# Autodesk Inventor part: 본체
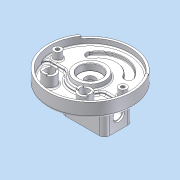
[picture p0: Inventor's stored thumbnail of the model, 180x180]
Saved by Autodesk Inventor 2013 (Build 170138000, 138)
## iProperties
Company: 한국ATC센터
Created: 2015-04
Part Number: 본체
Document SubType Name: Modeling
Designer: KYOUNG IL JANG
Density: 1 g/cm^3
Material: 일반
Mass: 494.771 g
Surface Area: 1387.34 cm^2
Volume: 494.771 cm^3
Author: KYOUNG IL JANG
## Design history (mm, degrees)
sketch "스케치1"
  geometry: L1 (-59, -19)-(-59, 19); L2 (59, 19)-(59, -19); L3 (-41, 19)-(-41, -19); L4 (41, -19)-(41, 19); L5 (38.527, 33.023)-(55.442, 39.179); L6 (-38.527, 33.023)-(-55.442, 39.179); C1 r 90 at (0, 0); C2 r 95 at (0, 0); A1 r 59 centre (0, 19) between (59, 19) and (-59, 19); A2 r 59 centre (0, -19) between (-59, -19) and (59, -19); A3 r 41 centre (0, -19) between (-41, -19) and (41, -19); A4 r 41 centre (0, 19) between (41, 19) and (-41, 19); 2 further points
  constraints: 12 end point, 12 point on circle, 6 centre point, 4 tangent, 2 parallel, 2 point on line, 1 coincident, 1 horizontal alignment, 1 midpoint, 1 vertical, 1 vertical alignment, 3 other
  dimensions: "d2" = 180 diameter of C1; "d3" = 156 dimension on A2 A1; "d4" = 118 distance between parallel lines of L2 L1; "d5" = 18 distance between parallel lines of L2 L4; "d8" = 190 diameter of C2; "d124" = 110 deg dimension on A1.centre point (0, 0) L5.end; "d125" = 140 deg angle of L5 L6
extrude "돌출1" new body sketch "스케치1" distance "d6" = 14; taper "d7" = 0 deg
extrude "돌출2" join sketch "스케치1" distance "d9" = 13; taper "d10" = 0 deg
extrude "돌출3" cut sketch "스케치1" distance "d11" = 7; taper "d12" = 0 deg
sketch "스케치2"
  geometry: C1 r 11.5 at (0, 0); 1 further point
  constraints: 1 centre point, 1 coincident
  dimensions: "d13" = 23 diameter of C1
extrude "돌출4" cut sketch "스케치2" stored distance "d14" = 7; taper "d15" = 0 deg
fillet "모깎기1"
fillet "모깎기2"
sketch "스케치3"
  geometry: L1 (-73.724, 51.622)-(-77.819, 54.49); L2 (73.724, 51.622)-(77.819, 54.49); L3 (0, 0)-(0, -90); A1 r 95 centre (0, 0) between (-77.819, 54.49) and (77.819, 54.49) reference; A2 r 90 centre (0, 0) between (-73.724, 51.622) and (73.724, 51.622) reference; 1 further point
  constraints: 6 end point, 5 point on circle, 1 point on line, 1 vertical, 1 other
  dimensions: "d16" = 250 deg dimension on L2 L1
extrude "돌출5" join sketch "스케치3" distance "d17" = 5; taper "d18" = 0 deg
hole "구멍1" diameter "d21" = 50; stored, may be unused: countersink angle "d25" = 90 deg, drill point angle "d27" = 0 deg; dims "d19" = 10, "d20" = 10, "d22" = 6, "d23" = 4, "d24" = 2, "d26" = 5
fillet "모깎기3" dims "d28" = 0.3
fillet "모깎기5" dims "d30" = 3
sketch "스케치4"
  geometry: C1 r 35 at (0, 0); C2 r 25 at (0, 0); 1 further point
  constraints: 2 centre point, 1 coincident
  dimensions: "d32" = 70 diameter of C1 (derived); "d36" = 10 radial gap between concentric circles of C1 C2
extrude "돌출6" join sketch "스케치4" distance "d33" = 10; taper "d34" = 0 deg
feature "면 기울기2" dims angle "d37" = 10 deg
chamfer "모따기1" distance "d39" = 1; stored, may be unused: second distance "d40" = 2, angle "d41" = 45 deg
fillet "모깎기7" dims "d42" = 5
sketch "스케치5"
  geometry: L1 (-40.249, -12)-(-89.196, -12); L2 (40.249, -12)-(89.196, -12); A1 r 90 centre (0, 0) between (-89.196, -12) and (89.196, -12) reference; A2 r 42 centre (0, 0) between (-40.249, -12) and (40.249, -12); 1 further point
  constraints: 4 end point, 4 point on circle, 1 centre point, 1 collinear, 1 horizontal, 1 point on line
  dimensions: "d43" = 48 radial gap between concentric circles of A1 A2; "d44" = 12 distance from line of point (0, 0) L1
extrude "돌출7" cut sketch "스케치5" stored distance "d45" = 10; taper "d46" = 0 deg
fillet "모깎기8" dims "d47" = 10
chamfer "모따기2" distance "d49" = 1; stored, may be unused: second distance "d50" = 2, angle "d51" = 45 deg
sketch "스케치8"
  geometry: C1 r 9 at (74, 0); C2 r 9 at (-74, 0); A1 r 74 centre (0, 0) between (74, 0) and (-74, 0); 1 further point
  constraints: 3 centre point, 2 horizontal alignment, 2 point on circle, 1 coincident, 1 equal radius
  dimensions: "d64" = 18 diameter of C1; "d65" = 148 diameter of A1
extrude "돌출9" join sketch "스케치8" stored distance "d66" = 5; taper "d67" = 0 deg
sketch "스케치11"
  geometry: C1 r 15 at (40, -52); C2 r 15 at (-40, -52); 1 further point
  constraints: 2 centre point, 1 equal radius, 1 horizontal alignment
  dimensions: "d82" = 52 vertical distance of point (0, 0) C1.centre; "d83" = 30 diameter of C1; "d84" = 80 distance of C2.centre C1.centre; "d85" = 40 horizontal distance of point (0, 0) C1.centre (= 0.5 x d84)
extrude "돌출10" join sketch "스케치11" stored distance "d86" = 10; taper "d87" = 0 deg
node "구멍3"
node "구멍5"
hole "구멍6" diameter "d92" = 20; stored, may be unused: countersink angle "d96" = 90 deg, drill point angle "d98" = 118 deg; dims "d90" = 10, "d91" = 10, "d93" = 6, "d94" = 4, "d95" = 2, "d97" = 8
hole "구멍7" diameter "d101" = 20; stored, may be unused: countersink angle "d105" = 90 deg, drill point angle "d107" = 118 deg; dims "d99" = 10, "d100" = 10, "d102" = 6, "d103" = 4, "d104" = 2, "d106" = 8
fillet "모깎기13" dims "d108" = 3
sketch "스케치13"
  geometry: L1 (-20.252, -58)-(-26, -58); L2 (-42, -58)-(-47.748, -58); L3 (-20.252, -46)-(-26, -46); L4 (-42, -46)-(-47.748, -46); L5 (-108, -65.748)-(-108, -60); L6 (-108, -44)-(-108, -38.252); L7 (-120, -44)-(-120, -38.252); L8 (-120, -60)-(-120, -65.748); A1 r 15 centre (-34, -52) between (-20.252, -58) and (-47.748, -58) reference; A2 r 10 centre (-34, -52) between (-26, -58) and (-42, -58) reference; A3 r 15 centre (-114, -52) between (-108, -65.748) and (-108, -38.252) reference; A4 r 10 centre (-114, -52) between (-108, -60) and (-108, -44) reference; 1 further point
  constraints: 16 end point, 16 point on circle, 3 equal length, 3 point on line, 2 collinear, 1 horizontal, 1 perpendicular
  dimensions: "d114" = 12 distance between parallel lines of L4 L2; "d115" = 6 distance from line of A1.centre L2 (= 0.5 x d114); "d116" = 12 distance between parallel lines of L8 L5 (= d114); "d117" = 6 distance from line of A3.centre L5 (= d115)
extrude "돌출12" join sketch "스케치13" distance "d118" = 3; taper "d119" = 0 deg
fillet "모깎기14" dims "d120" = 1
sketch "스케치14"
  geometry: L1 (23, 32.5)-(-53, 32.5); L2 (-65, 20.5)-(-65, -20.5); L3 (-53, -32.5)-(23, -32.5); L4 (35, -20.5)-(35, 20.5); L5 (30, 20.5)-(30, -20.5); L6 (23, -27.5)-(-53, -27.5); L7 (-60, -20.5)-(-60, 20.5); L8 (-53, 27.5)-(23, 27.5); A1 r 12 centre (-53, -20.5) between (-65, -20.5) and (-53, -32.5); A2 r 12 centre (-53, 20.5) between (-53, 32.5) and (-65, 20.5); A3 r 12 centre (23, 20.5) between (35, 20.5) and (23, 32.5); A4 r 12 centre (23, -20.5) between (23, -32.5) and (35, -20.5); A5 r 7 centre (23, -20.5) between (23, -27.5) and (30, -20.5); A6 r 7 centre (-53, -20.5) between (-60, -20.5) and (-53, -27.5); A7 r 7 centre (-53, 20.5) between (-53, 27.5) and (-60, 20.5); A8 r 7 centre (23, 20.5) between (30, 20.5) and (23, 27.5); A9 r 6 centre (-23, -25) between (-17.546, -27.5) and (-28.454, -27.5); A10 r 6 centre (-23, 25) between (-28.454, 27.5) and (-17.546, 27.5); 6 further points
  constraints: 20 point on circle, 16 end point, 12 point on line, 10 centre point, 8 tangent, 4 equal radius, 4 parallel, 2 perpendicular, 1 horizontal, 1 horizontal alignment, 1 midpoint, 1 vertical alignment, 7 other
  dimensions: "d126" = 35 distance from line of point (0, 0) L4; "d127" = 65 distance of point (35, -32.5) point (35, 32.5); "d128" = 100 distance of point (35, 32.5) point (-65, 32.5); "d132" = 12 radius of A1; "d133" = 5 distance between parallel lines of L5 L4; "d141" = 42 distance from line of A9.centre L2; "d142" = 12 diameter of A9; "d143" = 50 distance of A10.centre A9.centre; "d144" = 25 vertical distance of point (0, 0) A9.centre (= 0.5 x d143)
extrude "돌출13" join sketch "스케치14" distance "d130" = 58; taper "d131" = 0 deg
fillet "모깎기16" dims "d145" = 3
hole "구멍8" diameter "d148" = 4.134; stored, may be unused: countersink angle "d152" = 90 deg, drill point angle "d154" = 118 deg; dims "d146" = 10, "d147" = 10, "d149" = 12, "d150" = 4, "d151" = 2, "d153" = 15
hole "구멍9" diameter "d157" = 4.134; stored, may be unused: countersink angle "d161" = 90 deg, drill point angle "d163" = 118 deg; dims "d155" = 10, "d156" = 10, "d158" = 12, "d159" = 4, "d160" = 2, "d162" = 15
sketch "스케치17"
  geometry: L1 (-58, 110.5)-(-58, -69.5) reference; C1 r 15 at (-29.5, 20.5); 1 further point
  constraints: 1 centre point, 1 horizontal alignment
  dimensions: "d164" = 28.5 distance from line of C1.centre L1; "d165" = 30 diameter of C1
extrude "돌출16" join sketch "스케치17" distance "d166" = 28; taper "d167" = 0 deg
fillet "모깎기17" dims "d168" = 1
hole "구멍10" diameter "d171" = 22; stored, may be unused: countersink angle "d175" = 90 deg, drill point angle "d177" = 118 deg; dims "d169" = 10, "d170" = 10, "d172" = 12, "d173" = 26, "d174" = 4, "d176" = 15
node "솔리드1"
sketch "스케치9"
  geometry: 1 further point
hole "구멍2" sketch "스케치9" diameter "d68" = 8.376; stored, may be unused: countersink angle "d72" = 90 deg, drill point angle "d74" = 120 deg; dims "d69" = 16, "d70" = 4, "d71" = 2, "d73" = 21
sketch "스케치10"
  geometry: 1 further point
hole "구멍4" sketch "스케치10" diameter "d75" = 8.376; stored, may be unused: countersink angle "d79" = 90 deg, drill point angle "d81" = 120 deg; dims "d76" = 16, "d77" = 4, "d78" = 2, "d80" = 21
